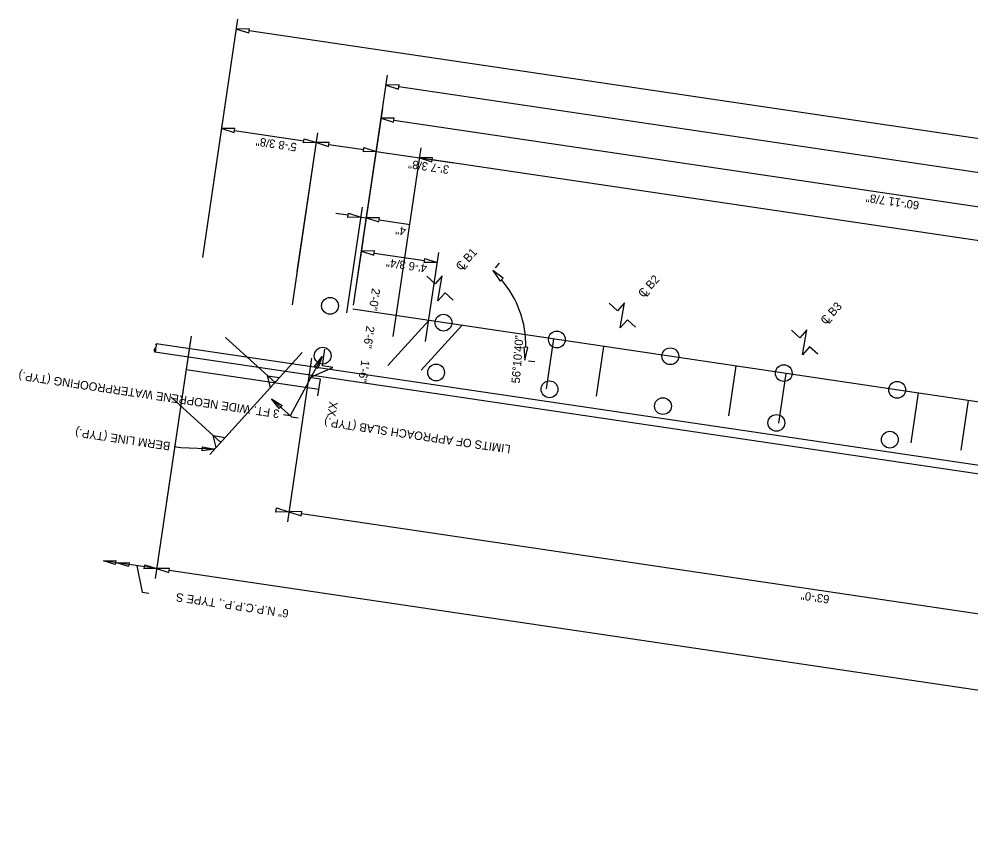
# Model space of a CAD drawing. Extents: x 1468952 to 1469933, y 573916 to 574220.
# Drawn here: x 1468952.5 to 1469009.2, y 573995.3 to 574044.2 of the extents above; entities that cross this region are included whole.
import ezdxf

# ---------------------------------------------------------------- set-up
doc = ezdxf.new("R2010")
doc.units = 0
for name, color, linetype in [('BR_P_Beam_Object', 7, 'Continuous'), ('BR_P_Gen_Centerline', 7, 'Continuous'), ('BR_P_Sub_Centerline', 7, 'Continuous'), ('BR_P_Sub_Deep_Centerline', 7, 'Continuous'), ('BR_X_SV_Beam_Seat', 7, 'Continuous'), ('Default', 7, 'Continuous'), ('SV_X_Text_Elevation', 7, 'Continuous')]:
    doc.layers.add(name, color=color, linetype=linetype)

# ---------------------------------------------------------------- blocks, each defined once
blk = doc.blocks.new('arrowOhio')
at = {"layer": 'Default'}
blk.add_lwpolyline([(0.00381, 0.000635), (0.00381, -0.000635), (0, 0)], close=True, dxfattribs=at)

msp = doc.modelspace()

# ---------------------------------------------------------------- linework, layer by layer
at = {"layer": 'BR_P_Beam_Object'}
for p, q in [((1468974.472, 574023.6), (1468976.9, 574026.274)), ((1468976.45, 574023.307), (1468978.878, 574025.981))]:
    msp.add_line(p, q, dxfattribs=at)
at = {"layer": 'BR_P_Gen_Centerline'}
for p, q in [((1469074.927, 574007.97), (1468960.648, 574024.889)), ((1469074.854, 574007.475), (1468960.574, 574024.394))]:
    msp.add_line(p, q, dxfattribs=at)
for centre, start, end in [((1468960.5, 574024.784), 307.976, 35.1816), ((1468960.723, 574024.498), 127.976, 215.1816), ((1468960.463, 574024.537), 307.976, 35.1816)]:
    msp.add_arc(centre, 0.181, start, end, dxfattribs=at)
at = {"layer": 'BR_P_Sub_Centerline'}
for centre in [(1468971.019, 574027.144), (1468977.779, 574026.143), (1468984.539, 574025.143), (1468970.58, 574024.176), (1468991.298, 574024.142), (1468977.34, 574023.176), (1468998.058, 574023.141), (1468984.099, 574022.175), (1469004.817, 574022.14), (1468990.859, 574021.174), (1468997.618, 574020.173), (1469004.378, 574019.173)]:
    msp.add_circle(centre, 0.5, dxfattribs=at)
at = {"layer": 'BR_P_Sub_Deep_Centerline'}
for p, q in [((1469066.452, 574013.016), (1468972.385, 574026.942)), ((1468984.344, 574025.171), (1468983.905, 574022.204)), ((1468987.312, 574024.732), (1468986.873, 574021.764)), ((1468995.21, 574023.563), (1468994.77, 574020.595)), ((1468998.177, 574023.123), (1468997.738, 574020.156)), ((1469006.075, 574021.954), (1469005.636, 574018.987)), ((1469009.043, 574021.515), (1469008.603, 574018.547))]:
    msp.add_line(p, q, dxfattribs=at)
at = {"layer": 'BR_X_SV_Beam_Seat'}
for p, q in [((1468974.778, 574025.314), (1468976.442, 574036.551)), ((1469062.525, 574023.201), (1468977.106, 574035.847)), ((1468962.736, 574025.338), (1468962.443, 574023.359)), ((1468967.743, 574022.575), (1468964.782, 574025.264)), ((1468969.362, 574024.357), (1468963.859, 574018.297)), ((1468962.466, 574023.518), (1468960.598, 574010.895)), ((1468962.443, 574023.359), (1468970.357, 574022.188)), ((1468964.506, 574019.01), (1468961.545, 574021.699)), ((1468960.686, 574011.489), (1468957.52, 574011.957)), ((1468959.499, 574011.664), (1468959.82, 574010.097)), ((1469070.257, 573995.267), (1468961.437, 574011.377)), ((1468959.82, 574010.097), (1468960.215, 574010.038))]:
    msp.add_line(p, q, dxfattribs=at)
for points in [[(1468977.087, 574035.721), (1468977.124, 574035.972), (1468976.354, 574035.958)], [(1468967.474, 574022.278), (1468967.299, 574022.978), (1468968.012, 574022.871)], [(1468964.237, 574018.714), (1468964.062, 574019.414), (1468964.775, 574019.306)], [(1468961.419, 574011.252), (1468961.456, 574011.503), (1468960.686, 574011.489)]]:
    msp.add_lwpolyline(points, close=True, dxfattribs=at)
at = {"layer": 'SV_X_Text_Elevation'}
for p, q in [((1468963.43, 574030.027), (1468965.533, 574044.232)), ((1469075.016, 574027.417), (1468966.197, 574043.527)), ((1468972.42, 574027.179), (1468974.45, 574040.89)), ((1469067.677, 574026.481), (1468975.114, 574040.185)), ((1468972.42, 574027.179), (1468974.157, 574038.911)), ((1468963.43, 574030.027), (1468964.654, 574038.296)), ((1468974.821, 574038.207), (1469033.645, 574029.498)), ((1468965.318, 574037.592), (1468969.451, 574036.98)), ((1468968.774, 574027.214), (1468970.291, 574037.462)), ((1468969.067, 574029.192), (1468970.291, 574037.462)), ((1468972.42, 574027.179), (1468973.864, 574036.933)), ((1468970.955, 574036.757), (1468973.024, 574036.451)), ((1468973.776, 574036.339), (1468978.394, 574035.656)), ((1468972.015, 574026.734), (1468972.947, 574033.025)), ((1468972.42, 574027.179), (1468973.278, 574032.976)), ((1468972.107, 574032.543), (1468971.355, 574032.654)), ((1468972.859, 574032.432), (1468973.19, 574032.383)), ((1468973.942, 574032.271), (1468975.803, 574031.996)), ((1468972.42, 574027.179), (1468972.985, 574030.998)), ((1468973.649, 574030.293), (1468976.655, 574029.848)), ((1468976.71, 574025.028), (1468977.495, 574030.33)), ((1468980.87, 574029.41), (1468981.121, 574029.686)), ((1468962.701, 574025.1), (1468961.257, 574015.347)), ((1468969.922, 574024.031), (1468968.478, 574014.278)), ((1468969.922, 574024.031), (1468968.478, 574014.278)), ((1468970.541, 574024.119), (1468968.638, 574020.601)), ((1468982.848, 574023.877), (1468983.217, 574023.822)), ((1468967.537, 574021.604), (1468968.721, 574020.528)), ((1468968.638, 574020.601), (1468968.242, 574020.66)), ((1468968.721, 574020.528), (1468969.117, 574020.469)), ((1468962.136, 574018.679), (1468961.74, 574018.737)), ((1468964.134, 574018.6), (1468962.136, 574018.679)), ((1469030.13, 574005.757), (1468969.318, 574014.76))]:
    msp.add_line(p, q, dxfattribs=at)
for points in [[(1468966.179, 574043.402), (1468966.216, 574043.652), (1468965.445, 574043.638)], [(1468975.095, 574040.06), (1468975.132, 574040.31), (1468974.362, 574040.296)], [(1468974.802, 574038.081), (1468974.839, 574038.332), (1468974.069, 574038.318)], [(1468965.3, 574037.466), (1468965.337, 574037.717), (1468964.567, 574037.703)], [(1468969.433, 574036.854), (1468969.47, 574037.105), (1468970.203, 574036.868)], [(1468970.936, 574036.632), (1468970.973, 574036.882), (1468970.203, 574036.868)], [(1468973.006, 574036.325), (1468973.043, 574036.576), (1468973.776, 574036.339)], [(1468972.088, 574032.418), (1468972.126, 574032.668), (1468972.859, 574032.432)], [(1468973.923, 574032.146), (1468973.961, 574032.397), (1468973.19, 574032.383)], [(1468973.631, 574030.168), (1468973.668, 574030.418), (1468972.897, 574030.404)], [(1468976.637, 574029.723), (1468976.674, 574029.973), (1468977.407, 574029.737)], [(1468981.156, 574028.608), (1468981.338, 574028.785), (1468980.718, 574029.242)], [(1468982.813, 574024.657), (1468982.561, 574024.678), (1468982.623, 574023.91)], [(1468967.795, 574014.857), (1468967.832, 574015.108), (1468968.566, 574014.871)], [(1468969.299, 574014.634), (1468969.336, 574014.885), (1468968.566, 574014.871)]]:
    msp.add_lwpolyline(points, close=True, dxfattribs=at)
for points in [[(1468978.361, 574027.482), (1468977.871, 574027.926), (1468977.441, 574027.453), (1468977.709, 574028.938), (1468977.279, 574028.464), (1468976.79, 574028.909)], [(1468989.226, 574025.873), (1468988.737, 574026.318), (1468988.307, 574025.844), (1468988.575, 574027.329), (1468988.145, 574026.856), (1468987.655, 574027.3)], [(1469000.092, 574024.265), (1468999.602, 574024.709), (1468999.172, 574024.235), (1468999.44, 574025.721), (1468999.01, 574025.247), (1468998.52, 574025.692)], [(1468970.298, 574021.792), (1468970.445, 574022.781), (1468969.812, 574022.875), (1468971.195, 574023.479), (1468970.562, 574023.573), (1468970.708, 574024.562)]]:
    msp.add_lwpolyline(points, dxfattribs=at)
msp.add_arc((1468976.675, 574024.79), 6.013, 358.825, 40.5103, dxfattribs=at)

# ---------------------------------------------------------------- block references
at = {"layer": 'BR_X_SV_Beam_Seat', "xscale": 191.49568000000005, "yscale": 191.49568}
for p, rotation in [((1468957.52, 574011.957), -8.421230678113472), ((1468958.312, 574011.84), -8.421230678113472), ((1468960.686, 574011.489), 171.57876932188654)]:
    msp.add_blockref('arrowOhio', p, dxfattribs=dict(at, rotation=rotation))
at = {"layer": 'SV_X_Text_Elevation'}
for p, xscale, yscale, rotation in [((1468970.541, 574024.119), 191.49568, 191.49568, -118.42123067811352), ((1468967.537, 574021.604), 191.49568, 191.49568, -42.243452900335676), ((1468964.134, 574018.6), 191.49568000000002, 191.49568000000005, 177.75654709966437)]:
    msp.add_blockref('arrowOhio', p, dxfattribs=dict(at, xscale=xscale, yscale=yscale, rotation=rotation))

# ---------------------------------------------------------------- texts
for s, rotation, p in [('5\'-8 3/8"', 171.5788, (1468969.064, 574036.835)), ('3\'-7 3/8"', 171.5788, (1468978.147, 574035.49)), ('60\'-11 7/8"', 171.5788, (1469006.155, 574033.365)), ('4"', 171.5788, (1468975.569, 574031.828)), ('C B1', 47.7565, (1468978.831, 574029.206)), ('4\'-6 3/4"', 171.5788, (1468976.827, 574029.62)), ('L', 47.7565, (1468979.006, 574029.25)), ('C B2', 47.7565, (1468989.696, 574027.598)), ('2\'-0"', 261.5788, (1468973.524, 574028.219)), ('L', 47.7565, (1468989.871, 574027.641)), ('C B3', 47.7565, (1469000.562, 574025.989)), ('L', 47.7565, (1469000.737, 574026.033)), ('2\'-6"', 261.5788, (1468973.191, 574025.973)), ('56°10\'40"', 85.3928, (1468982.323, 574022.51)), ('1\'-6"', 261.5788, (1468972.89, 574023.938)), ('3 FT. WIDE NEOPRENE WATERPROOFING (TYP.)', 171.5788, (1468968.031, 574020.944)), ('XX', 261.5788, (1468970.985, 574021.475)), ('LIMITS OF APPROACH SLAB (TYP.)', 171.5788, (1468981.807, 574018.843)), ('BERM LINE (TYP.)', 171.5788, (1468961.529, 574019.021)), ('6" N.P.C.P.P., TYPE S', 171.5788, (1468968.584, 574009.052)), ('63\'-0"', 171.5788, (1469000.809, 574009.895))]:
    msp.add_text(s, height=0.5, rotation=rotation, dxfattribs=at).set_placement(p)

doc.saveas('drawing.dxf')
